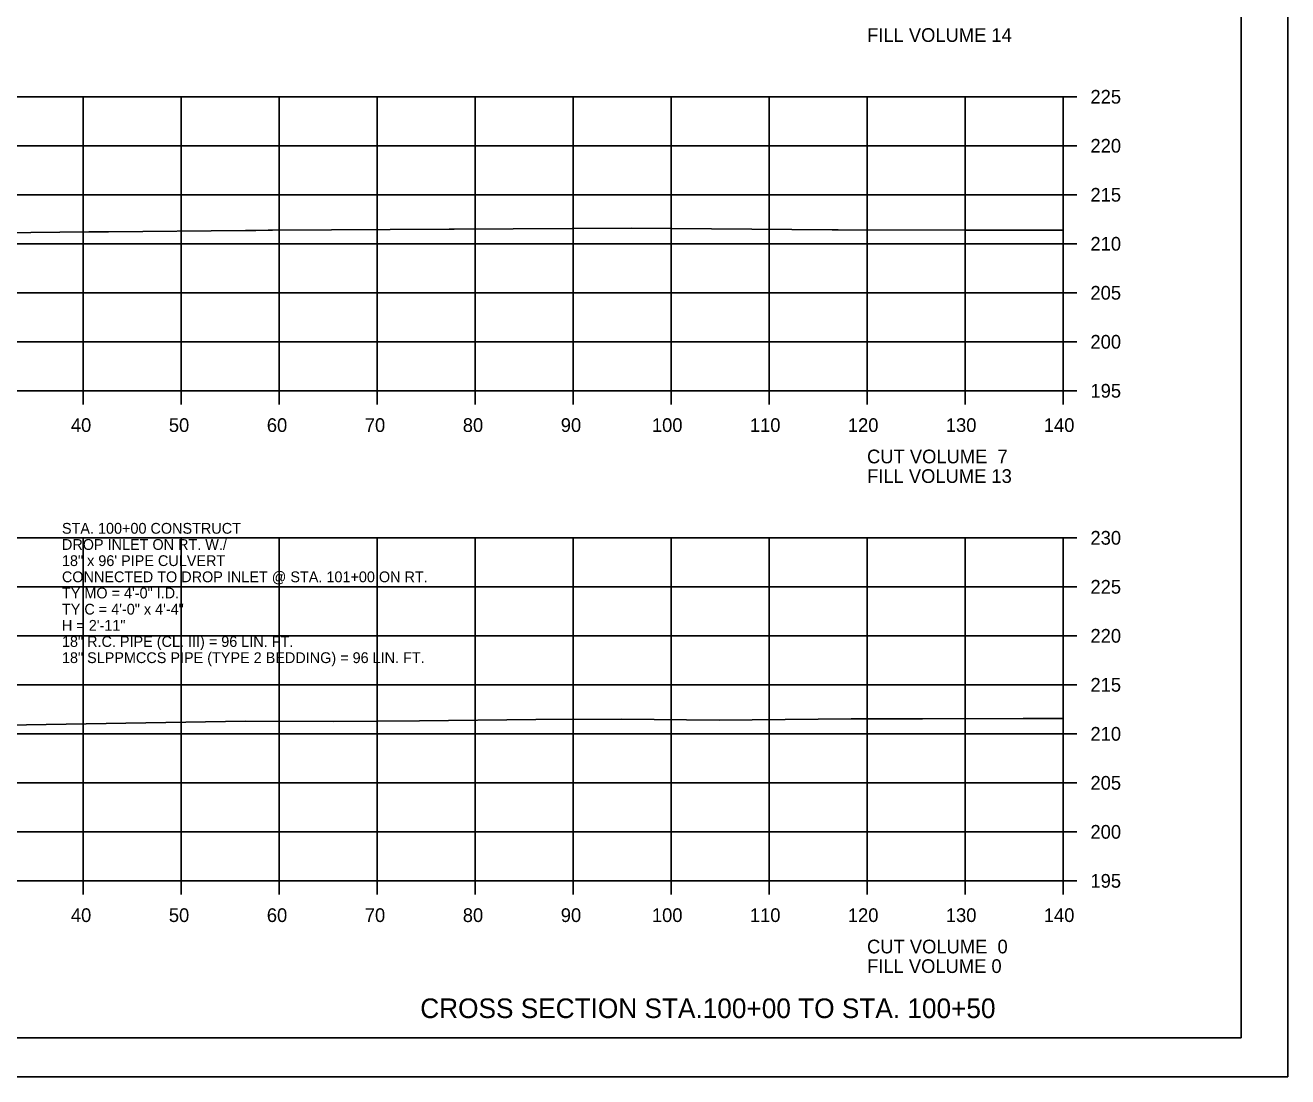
# Model space of a CAD drawing. Extents: x 1368968 to 1369915, y 377395 to 380381.
# Drawn here: x 1369172.2 to 1369301.1, y 377407.7 to 377515 of the extents above; entities that cross this region are included whole.
import ezdxf

# ---------------------------------------------------------------- set-up
doc = ezdxf.new("R2010")
doc.units = 0
for name, color, linetype in [('Default', 7, 'Continuous'), ('S_BREAKLINE_ANNOT', 7, 'Continuous'), ('S_BRIDGE', 7, 'Continuous'), ('S_BRIDGE_ANNOT', 7, 'Continuous'), ('S_CONTOUR_MINOR', 7, 'Continuous'), ('S_CTL_TABLE', 7, 'Continuous'), ('S_DITCHLINE_ANNOT', 7, 'Continuous'), ('S_DROP_INLET', 7, 'Continuous')]:
    doc.layers.add(name, color=color, linetype=linetype)

msp = doc.modelspace()

# ---------------------------------------------------------------- linework, layer by layer
at = {"layer": 'S_BREAKLINE_ANNOT'}
for p, q in [((1369278.13, 377477.68), (1369278.13, 377507.68)), ((1369279.53, 377507.68), (1369278.13, 377507.68)), ((1369279.53, 377502.68), (1369278.13, 377502.68)), ((1369279.53, 377497.68), (1369278.13, 377497.68)), ((1369279.53, 377492.68), (1369278.13, 377492.68)), ((1369279.53, 377487.68), (1369278.13, 377487.68)), ((1369279.53, 377482.68), (1369278.13, 377482.68)), ((1368998.13, 377477.68), (1369278.13, 377477.68)), ((1369178.13, 377476.28), (1369178.13, 377477.68)), ((1369188.13, 377476.28), (1369188.13, 377477.68)), ((1369198.13, 377476.28), (1369198.13, 377477.68)), ((1369208.13, 377476.28), (1369208.13, 377477.68)), ((1369218.13, 377476.28), (1369218.13, 377477.68)), ((1369228.13, 377476.28), (1369228.13, 377477.68)), ((1369238.13, 377476.28), (1369238.13, 377477.68)), ((1369248.13, 377476.28), (1369248.13, 377477.68)), ((1369258.13, 377476.28), (1369258.13, 377477.68)), ((1369268.13, 377476.28), (1369268.13, 377477.68)), ((1369278.13, 377476.28), (1369278.13, 377477.68)), ((1369279.53, 377477.68), (1369278.13, 377477.68)), ((1369278.13, 377427.68), (1369278.13, 377462.68)), ((1369279.53, 377462.68), (1369278.13, 377462.68)), ((1369279.53, 377457.68), (1369278.13, 377457.68)), ((1369279.53, 377452.68), (1369278.13, 377452.68)), ((1369279.53, 377447.68), (1369278.13, 377447.68)), ((1369279.53, 377442.68), (1369278.13, 377442.68)), ((1369279.53, 377437.68), (1369278.13, 377437.68)), ((1369279.53, 377432.68), (1369278.13, 377432.68)), ((1368998.13, 377427.68), (1369278.13, 377427.68)), ((1369178.13, 377426.28), (1369178.13, 377427.68)), ((1369188.13, 377426.28), (1369188.13, 377427.68)), ((1369198.13, 377426.28), (1369198.13, 377427.68)), ((1369208.13, 377426.28), (1369208.13, 377427.68)), ((1369218.13, 377426.28), (1369218.13, 377427.68)), ((1369228.13, 377426.28), (1369228.13, 377427.68)), ((1369238.13, 377426.28), (1369238.13, 377427.68)), ((1369248.13, 377426.28), (1369248.13, 377427.68)), ((1369258.13, 377426.28), (1369258.13, 377427.68)), ((1369268.13, 377426.28), (1369268.13, 377427.68)), ((1369278.13, 377426.28), (1369278.13, 377427.68)), ((1369279.53, 377427.68), (1369278.13, 377427.68))]:
    msp.add_line(p, q, dxfattribs=at)
at = {"layer": 'S_BRIDGE_ANNOT'}
for q in [(1369296.31, 377617.14), (1368980.13, 377411.68)]:
    msp.add_line((1369296.31, 377411.68), q, dxfattribs=at)
at = {"layer": 'S_CTL_TABLE'}
for points in [[(1369169.84, 377493.81), (1369178.69, 377493.89), (1369180.71, 377493.9), (1369194.68, 377494.03), (1369195.76, 377494.04), (1369197.01, 377494.06), (1369197.44, 377494.06), (1369215.47, 377494.17), (1369215.98, 377494.18), (1369234.05, 377494.29), (1369254.58, 377494.09), (1369255.17, 377494.09), (1369268.19, 377494.08), (1369268.59, 377494.08), (1369278.13, 377494.08)], [(1369168.24, 377443.54), (1369194.68, 377443.96), (1369203.68, 377443.95), (1369212.45, 377444), (1369224.33, 377444.13), (1369233.08, 377444.18), (1369243.03, 377444.08), (1369256.5, 377444.21), (1369263.78, 377444.21), (1369274.05, 377444.26), (1369278.13, 377444.26)]]:
    msp.add_lwpolyline(points, dxfattribs=at)
at = {"layer": 'S_DITCHLINE_ANNOT'}
for p, q in [((1368998.13, 377507.68), (1369278.13, 377507.68)), ((1369178.13, 377477.68), (1369178.13, 377507.68)), ((1369188.13, 377477.68), (1369188.13, 377507.68)), ((1369198.13, 377477.68), (1369198.13, 377507.68)), ((1369208.13, 377477.68), (1369208.13, 377507.68)), ((1369218.13, 377477.68), (1369218.13, 377507.68)), ((1369228.13, 377477.68), (1369228.13, 377507.68)), ((1369238.13, 377477.68), (1369238.13, 377507.68)), ((1369248.13, 377477.68), (1369248.13, 377507.68)), ((1369258.13, 377477.68), (1369258.13, 377507.68)), ((1369268.13, 377477.68), (1369268.13, 377507.68)), ((1369278.13, 377477.68), (1369278.13, 377507.68)), ((1368998.13, 377502.68), (1369278.13, 377502.68)), ((1368998.13, 377497.68), (1369278.13, 377497.68)), ((1368998.13, 377492.68), (1369278.13, 377492.68)), ((1368998.13, 377487.68), (1369278.13, 377487.68)), ((1368998.13, 377482.68), (1369278.13, 377482.68)), ((1368998.13, 377477.68), (1369278.13, 377477.68)), ((1368998.13, 377462.68), (1369278.13, 377462.68)), ((1369178.13, 377427.68), (1369178.13, 377462.68)), ((1369188.13, 377427.68), (1369188.13, 377462.68)), ((1369198.13, 377427.68), (1369198.13, 377462.68)), ((1369208.13, 377427.68), (1369208.13, 377462.68)), ((1369218.13, 377427.68), (1369218.13, 377462.68)), ((1369228.13, 377427.68), (1369228.13, 377462.68)), ((1369238.13, 377427.68), (1369238.13, 377462.68)), ((1369248.13, 377427.68), (1369248.13, 377462.68)), ((1369258.13, 377427.68), (1369258.13, 377462.68)), ((1369268.13, 377427.68), (1369268.13, 377462.68)), ((1369278.13, 377427.68), (1369278.13, 377462.68)), ((1368998.13, 377457.68), (1369278.13, 377457.68)), ((1368998.13, 377452.68), (1369278.13, 377452.68)), ((1368998.13, 377447.68), (1369278.13, 377447.68)), ((1368998.13, 377442.68), (1369278.13, 377442.68)), ((1368998.13, 377437.68), (1369278.13, 377437.68)), ((1368998.13, 377432.68), (1369278.13, 377432.68)), ((1368998.13, 377427.68), (1369278.13, 377427.68))]:
    msp.add_line(p, q, dxfattribs=at)
at = {"layer": 'S_DROP_INLET'}
msp.add_line((1368967.73, 377407.7), (1369301.07, 377407.7), dxfattribs=at)
for points in [[(1368967.73, 377621.03), (1369301.07, 377621.03), (1369301.07, 377407.69), (1368967.73, 377407.69)], [(1369214.05, 377617.14), (1369214.05, 377607.26), (1369249.79, 377607.26), (1369249.79, 377604.34), (1369272.99, 377604.34), (1369272.99, 377580), (1369296.31, 377580), (1369296.31, 377411.68), (1368980.13, 377411.68), (1368980.13, 377617.14)]]:
    msp.add_lwpolyline(points, close=True, dxfattribs=at)

# ---------------------------------------------------------------- texts
at = {"layer": 'Default'}
for s, p in [('STA. 100+00 CONSTRUCT', (1369175.96, 377463.1)), ('DROP INLET ON RT. W./', (1369175.96, 377461.45)), ('18" x 96\' PIPE CULVERT  ', (1369175.96, 377459.8)), ('CONNECTED TO DROP INLET @ STA. 101+00 ON RT.', (1369175.96, 377458.15)), ('TY MO = 4\'-0" I.D.', (1369175.96, 377456.5)), ('TY C = 4\'-0" x 4\'-4"', (1369175.96, 377454.85)), ('H = 2\'-11"', (1369175.96, 377453.2)), ('18" R.C. PIPE (CL. III) = 96 LIN. FT.', (1369175.96, 377451.55)), ('18" SLPPMCCS PIPE (TYPE 2 BEDDING) = 96 LIN. FT.', (1369175.96, 377449.9))]:
    msp.add_text(s, height=1.1, dxfattribs=at).set_placement(p)
at = {"layer": 'S_BRIDGE'}
for s, p in [('FILL VOLUME 14', (1369258.13, 377513.28)), ('225', (1369280.93, 377506.98)), ('220', (1369280.93, 377501.98)), ('215', (1369280.93, 377496.98)), ('210', (1369280.93, 377491.98)), ('205', (1369280.93, 377486.98)), ('200', (1369280.93, 377481.98)), ('195', (1369280.93, 377476.98)), ('40', (1369176.87, 377473.48)), ('50', (1369186.87, 377473.48)), ('60', (1369196.87, 377473.48)), ('70', (1369206.87, 377473.48)), ('80', (1369216.87, 377473.48)), ('90', (1369226.87, 377473.48)), ('100', (1369236.17, 377473.48)), ('110', (1369246.17, 377473.48)), ('120', (1369256.17, 377473.48)), ('130', (1369266.17, 377473.48)), ('140', (1369276.17, 377473.48)), ('CUT VOLUME  7', (1369258.13, 377470.28)), ('FILL VOLUME 13', (1369258.13, 377468.28)), ('230', (1369280.93, 377461.98)), ('225', (1369280.93, 377456.98)), ('220', (1369280.93, 377451.98)), ('215', (1369280.93, 377446.98)), ('210', (1369280.93, 377441.98)), ('205', (1369280.93, 377436.98)), ('200', (1369280.93, 377431.98)), ('195', (1369280.93, 377426.98)), ('40', (1369176.87, 377423.48)), ('50', (1369186.87, 377423.48)), ('60', (1369196.87, 377423.48)), ('70', (1369206.87, 377423.48)), ('80', (1369216.87, 377423.48)), ('90', (1369226.87, 377423.48)), ('100', (1369236.17, 377423.48)), ('110', (1369246.17, 377423.48)), ('120', (1369256.17, 377423.48)), ('130', (1369266.17, 377423.48)), ('140', (1369276.17, 377423.48)), ('CUT VOLUME  0', (1369258.13, 377420.28)), ('FILL VOLUME 0', (1369258.13, 377418.28))]:
    msp.add_text(s, height=1.4, dxfattribs=at).set_placement(p)
at = {"layer": 'S_CONTOUR_MINOR'}
msp.add_text('CROSS SECTION STA.100+00 TO STA. 100+50', height=2, dxfattribs=at).set_placement((1369212.53, 377413.68))

doc.saveas('drawing.dxf')
